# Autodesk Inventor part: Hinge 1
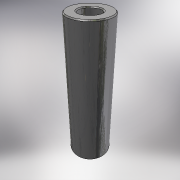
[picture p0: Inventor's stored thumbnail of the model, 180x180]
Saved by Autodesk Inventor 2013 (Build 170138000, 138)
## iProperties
Shininess: 64.0
Length Units: 11269
Angle Units: 11279
Time Units: 11290
Mass Units: 11283
Length Display Precision: 3
Angle Display Precision: 2
Compacted: True
Part Number: Hinge 1
Document SubType Name: Modeling
Created: 2004-11
Material: Stainless Steel, 440C
Designer: =<Author>
Manufacturer: Standard
Standards Organization: Custom
Description: bush
Density: 7.75 g/cm^3
Mass: 127.641 g
Surface Area: 70.1337 cm^2
Volume: 16.4698 cm^3
Density: 0.0
Volumn: 0.0
Area: 0.0
PropertySet Name: Model Information
Control State: 0
Master: False
Checked Out: False
Checked Out Date: 2008-10-15
Last Check In Date: 2008-10-15
d0: 20.000 mm
d1: 10.000 mm
d2: 70.000 mm
d3: 0.00 deg
d4: 0.500 mm
Author: PVitaliy
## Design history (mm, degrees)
sketch "Эскиз1"
  geometry: C1 r 10 at (0, 0); C2 r 5 at (0, 0)
  constraints: 2 centre point, 1 coincident, 1 other
  dimensions: "d0" = 20 diameter of C1; "d1" = 10 diameter of C2
extrude "Выдавливание1" new body sketch "Эскиз1" distance "d2" = 70; taper "d3" = 0 deg
chamfer "Фаска1" distance "d4" = 0.5; stored, may be unused: second distance "d5" = 2, angle "d6" = 45 deg
body "Solid1"
